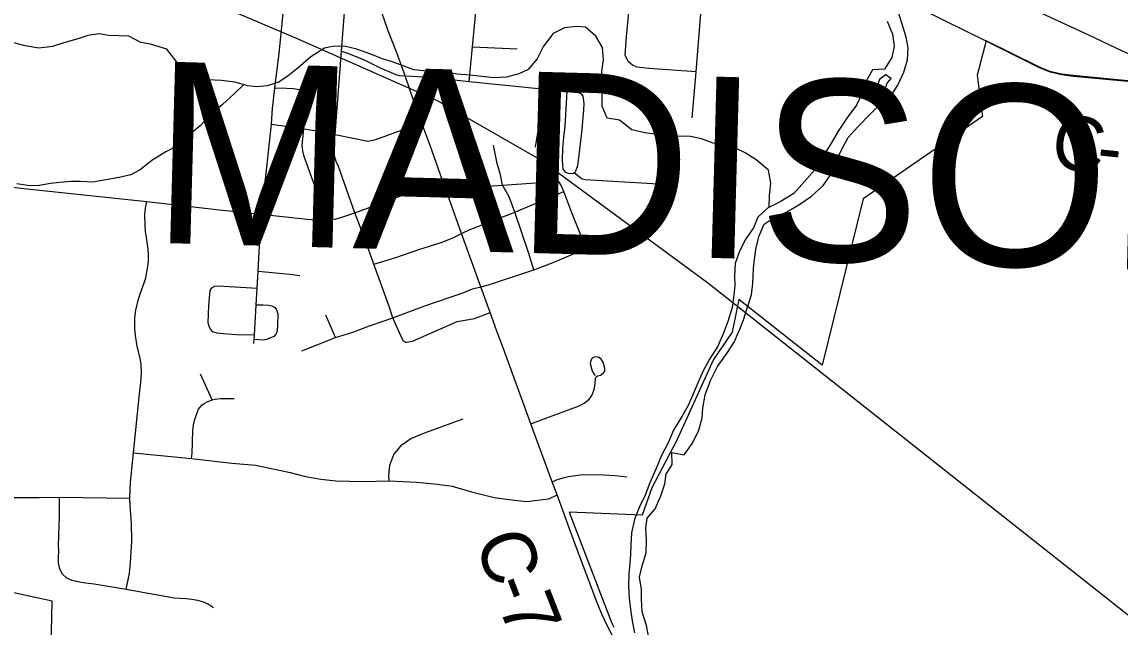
# Model space of a CAD drawing. Extents: x 114843 to 284848, y 317643 to 566895.
# Drawn here: x 129491 to 135543, y 436168 to 439505 of the extents above; entities that cross this region are included whole.
import ezdxf

# ---------------------------------------------------------------- set-up
doc = ezdxf.new("R2010")
doc.units = 0
for name, color, linetype in [('GM_X_City_Street', 7, 'Continuous'), ('GM_X_Corporation', 7, 'Continuous'), ('GM_X_County_Road', 7, 'Continuous'), ('GM_X_County_Road_Text', 7, 'Continuous'), ('GM_X_County_Text', 7, 'Continuous'), ('GM_X_Major_River', 7, 'Continuous'), ('GM_X_Minor_River', 7, 'Continuous'), ('GM_X_Rail_Line', 7, 'Continuous'), ('GM_X_State_Route', 7, 'Continuous')]:
    doc.layers.add(name, color=color, linetype=linetype)

msp = doc.modelspace()

# ---------------------------------------------------------------- linework, layer by layer
at = {"layer": 'GM_X_City_Street'}
for p, q in [((131974, 439367.9), (132221.3, 439357.5)), ((131219.3, 437764.1), (131166.5, 437887.7)), ((130539.9, 437421.5), (130475.5, 437562))]:
    msp.add_line(p, q, dxfattribs=at)
for points in [[(130808.9, 438444.4), (130818.4, 438511.8), (130840.9, 438705.1), (130865.5, 438942.2), (130872.7, 439027.6), (130885.3, 439140.6), (130908.8, 439332.6), (130936.7, 439607.5), (130946.1, 439685.4), (130964.3, 439843.2), (130982.9, 440026.2), (130985, 440064.6)], [(131605.6, 437738.7), (131600.2, 437740.5), (131594.5, 437745.9), (131589.3, 437753.8), (131535.3, 437873.4), (131512.5, 437942.1), (131430.5, 438169.5), (131379.9, 438309.9), (131326, 438452.4), (131235.2, 438707.1), (131222.1, 438736.4), (131212.7, 438767.2), (131207, 438799), (131217.8, 438883.9), (131251.6, 439343.4), (131276.1, 439653.8), (131289.2, 439816.3), (131292, 440035.2)], [(131955.1, 439176.1), (131974, 439367.9), (131992.9, 439561.3), (132010.4, 439750.3), (132022.1, 439864.4), (132028.3, 439962.7)], [(132832.5, 439286.8), (132816.2, 439321.9), (132823.7, 439422.2), (132867.9, 439881.6)], [(133184.6, 438976.9), (133206.8, 439229.7), (133232.2, 439551.5), (133253.3, 439749.9), (133267.4, 439843.6)], [(131251.6, 439343.4), (131285.6, 439332.7), (131373.4, 439297.1), (131464.9, 439252.8), (131551.8, 439216), (131570.6, 439210.5), (131602.7, 439207.3), (131743.3, 439201.1), (131955.1, 439176.1), (132355.9, 439135.7), (132496.3, 439121.9), (132553.1, 439116.9), (132565.7, 439113.5), (132575.4, 439107.7), (132582.1, 439096.4), (132588, 439055.2), (132586.9, 439018.2), (132574.8, 438895.4), (132556.7, 438741.8), (132552.1, 438711), (132540.3, 438675.9), (132536.2, 438672.9)], [(133206.8, 439229.7), (132945.5, 439247.7), (132879.8, 439256.5), (132855.6, 439265.8), (132832.5, 439286.8)], [(131176.6, 438412.6), (131094.3, 438630), (131046.5, 438763.4), (131039.9, 438794.6), (131036, 438826.4), (131044.5, 438916.3), (131064.3, 439082.1), (131066.4, 439113.2), (131064.3, 439115.8), (131039.1, 439125.2), (131009.6, 439132.4), (130987.1, 439135.7), (130948.9, 439138.6), (130885.3, 439140.6)], [(132355.9, 439135.7), (132355.2, 439069.2), (132341.3, 438995.8), (132338.6, 438975.6), (132333.9, 438904.9), (132320.2, 438814.9)], [(132536.2, 438672.9), (132530.4, 438668.5), (132513, 438668), (132503, 438669), (132489.1, 438675.5), (132478.9, 438685.1), (132474.8, 438693.1), (132472, 438715.5), (132470.8, 438746.2), (132472.6, 438807.8), (132478, 438869.3), (132485.5, 438930.6), (132496.3, 439121.9)], [(130865.5, 438942.2), (131044.5, 438916.3), (131129.9, 438903.2), (131217.8, 438883.9), (131396.9, 438848.4), (131433.3, 438855.1), (131488.1, 438872.7), (131552.3, 438897.4), (131694.5, 438947)], [(132311.9, 438138.6), (132282.5, 438233), (132206.8, 438456.5), (132175.8, 438540.3), (132139.8, 438604.1), (132128.5, 438661.4), (132109.9, 438724.9), (132090.8, 438825.1)], [(128022.6, 438748.3), (128278.4, 438722.7), (128595.2, 438687.5), (129311.7, 438607.9), (129484.1, 438588.2), (130178.3, 438514.1), (130580.1, 438468.7), (130808.9, 438444.4), (131062.1, 438417.6), (131126.5, 438412.5), (131176.6, 438412.6), (131191.4, 438413.5), (131223.2, 438419.9), (131254.8, 438428.4), (131326, 438452.4), (131809, 438630.5)], [(132536.2, 438672.9), (132579.1, 438639.9), (132594.9, 438636), (133059.7, 438609.1)], [(131826.6, 438580.3), (131928.3, 438589.5), (132139.8, 438604.1), (132320.6, 438617.4), (132419.9, 438629.6), (132436.4, 438629.5), (132448.5, 438627.2)], [(132603, 438251.3), (132521.9, 438452.7), (132477.6, 438569.5), (132462.8, 438604), (132448.5, 438627.2)], [(131430.5, 438169.5), (131556.6, 438208.6), (131679, 438250), (131802.1, 438289.5), (131862.7, 438312.4), (131913.8, 438338.9), (131955.8, 438359.6), (132189.7, 438448.5), (132206.8, 438456.5), (132477.6, 438569.5)], [(130066, 436377.4), (130078.5, 436437.4), (130082.8, 436466.3), (130088.3, 436524.5), (130095.7, 436641), (130095, 436739.3), (130086.6, 436837), (130084.8, 436878.1), (130089.4, 436967.4), (130105, 437129.9), (130138.5, 437454.6), (130146.4, 437519.4), (130149.5, 437567.6), (130147.5, 437617.1), (130142.2, 437649.3), (130126.3, 437717.8), (130116.6, 437776.8), (130112.9, 437816.2), (130113.9, 437874), (130118.9, 437915.5), (130131.5, 437969.7), (130140.4, 438000.9), (130172.9, 438092.5), (130176.2, 438106.2), (130185.1, 438156), (130188.3, 438188.2), (130188.1, 438220.6), (130185.9, 438252.9), (130178, 438317.1), (130171.2, 438350), (130169.2, 438380.5), (130168.9, 438445.8), (130171.8, 438478.1), (130178.3, 438514.1)], [(130769, 437731.1), (130770.4, 437754.4), (130771.7, 437777), (130781.7, 437944.8), (130787.6, 438036.6), (130792.6, 438131.1), (130808.9, 438444.4)], [(132020.3, 438045.1), (132061.6, 438055.5), (132311.9, 438138.6), (132419.3, 438178.4), (132539.3, 438229.5), (132603, 438251.3), (132814, 438341.3)], [(130792.6, 438131.1), (130967.1, 438114.3), (131021.8, 438107.4)], [(130771.7, 437777), (130672.9, 437780.4), (130599.9, 437784.8), (130565.9, 437788.2), (130542.7, 437796.5), (130530.5, 437811), (130521.9, 437826.7), (130518.1, 437846.2), (130521, 437942.2), (130527.7, 438024.9), (130537.4, 438039.5), (130553.1, 438048.2), (130572.5, 438049.5), (130787.6, 438036.6)], [(131033.9, 437690.9), (131219.3, 437764.1), (131315, 437794.4), (131406.1, 437828.8), (131535.3, 437873.4), (131711.7, 437939.1), (131927.1, 438012.6), (131973.9, 438033.4), (132020.3, 438045.1)], [(130781.7, 437944.8), (130821, 437945.1), (130849.2, 437943.3), (130868.6, 437939.8), (130884.5, 437930.2), (130894.3, 437918.1), (130901.8, 437896.3), (130899.3, 437833.5), (130897.1, 437801.5), (130892.8, 437785.7), (130878.4, 437771), (130838.4, 437753.7), (130820.8, 437750.9), (130770.4, 437754.4)], [(131605.6, 437738.7), (131611.6, 437738.6), (131643.6, 437745.5), (131890.3, 437853.1), (131984.6, 437869.5), (132071.5, 437903.3)], [(132296.2, 437288.5), (132384.7, 437322.9), (132562, 437388.6), (132590.5, 437403.1), (132615.2, 437422.9), (132625.4, 437435), (132633.6, 437448.3), (132644.7, 437478), (132649.5, 437509.6), (132651.3, 437538.1), (132655.9, 437548.1), (132662.8, 437554.2), (132680.3, 437558), (132694.8, 437567.6), (132702.8, 437579.3), (132703.4, 437593.9), (132694.4, 437628.1), (132684.1, 437646.3), (132668.7, 437656.4), (132650.4, 437657.7), (132633.7, 437650.3), (132626.5, 437638.6), (132623.7, 437622.5), (132631.2, 437586.8), (132641.6, 437567.2), (132650.4, 437554.9)], [(130425, 437097.8), (130428.3, 437127.8), (130432.3, 437250.3), (130435.9, 437281), (130443.1, 437313.9), (130464.1, 437370.3), (130482.5, 437392.6), (130494.9, 437401.9), (130508, 437409.2), (130539.9, 437421.5), (130556.7, 437425.5), (130585.2, 437428.1), (130659.8, 437428.7)], [(131515.5, 436974.3), (131513, 436999.7), (131517.7, 437061), (131540.7, 437119.7), (131584.2, 437172.7), (131633.8, 437208.2), (131715.5, 437240.9), (131922.7, 437315.6)], [(130105, 437129.9), (130425, 437097.8), (130647.5, 437071.3), (130780, 437061.6), (130970, 437019.7), (131053.2, 436998.1), (131137.6, 436982.9), (131221, 436974.6), (131370.4, 436970.1), (131515.5, 436974.3), (131667.1, 436967.5), (131781.3, 436956.4), (131862.7, 436944.5), (131968.8, 436913.9), (132094.4, 436883.5), (132161.8, 436872.9), (132221.9, 436865.4), (132272.5, 436861.1), (132394.1, 436875.8), (132441.1, 436896.6)], [(132414.1, 436969.7), (132443.5, 436982.1), (132473.5, 436991.8), (132503.7, 436998.9), (132567.9, 437007), (132631.9, 437008.8), (132696, 437007.7), (132760, 437003.2), (132824.2, 436996.6)], [(128955.7, 436827.1), (128993.1, 436853.6), (129032.2, 436871.9), (129072.6, 436884.9), (129095.6, 436890), (129130, 436894.6), (129171.4, 436895.7), (129388.4, 436882.8), (129584.8, 436882.9), (129696.8, 436884.6), (130084.8, 436878.1)], [(129696.8, 436884.6), (129695.9, 436780), (129691.3, 436618.3), (129692.1, 436586), (129689.7, 436553.8), (129690.5, 436521.4), (129698.1, 436490.1), (129712.9, 436461.7), (129736, 436440.5), (129765.8, 436427.7), (129827.4, 436414.8), (129858.1, 436409.9), (129889.6, 436407), (130066, 436377.4), (130330.4, 436330.3), (130393.8, 436326.2), (130426.5, 436322.5), (130458.5, 436316.5), (130489.7, 436307.2), (130519.4, 436294), (130547.2, 436276.5)]]:
    msp.add_lwpolyline(points, dxfattribs=at)
at = {"layer": 'GM_X_Corporation'}
for points in [[(135643.3, 439175.5), (135285.3, 439208.9), (135220.6, 439218), (135156.9, 439232.7), (135096.2, 439257.6), (134806.5, 439401.1), (134755.3, 439210.7), (134785.4, 438984.2), (134128.4, 438529), (133901.8, 437611.9), (133442.1, 437973.9), (133405.4, 437794.3), (133303.5, 437643.3), (133099.8, 437198.2), (132962.4, 436936.5), (132909, 436785.9), (132506.8, 436802.2), (132670.8, 436374.9), (132742, 436189.3), (132753.3, 436167.7)], [(129645, 435715.4), (129656.5, 436310.5), (128946.9, 436465.4)]]:
    msp.add_lwpolyline(points, dxfattribs=at)
at = {"layer": 'GM_X_County_Road'}
for p, q in [((131826.6, 438580.3), (131809, 438630.5)), ((131913.8, 438338.9), (131826.6, 438580.3)), ((132020.3, 438045.1), (131913.8, 438338.9)), ((132071.5, 437903.3), (132020.3, 438045.1)), ((132414.1, 436969.7), (132296.2, 437288.5)), ((132441.1, 436896.6), (132414.1, 436969.7))]:
    msp.add_line(p, q, dxfattribs=at)
for points in [[(131602.7, 439207.3), (131557.2, 439335.2), (131509.1, 439456.5), (131456.3, 439611), (131411.7, 439733.8), (131387.4, 439808.8)], [(134265.5, 439747.4), (134287.9, 439722.2), (134326.2, 439672.3), (134347.5, 439647.5), (134453.7, 439573.6), (134807.7, 439398.2)], [(134807.7, 439398.2), (135097.4, 439254.7), (135158.1, 439229.9), (135221.8, 439215.2), (135286.5, 439206.1), (135644.5, 439172.7), (135883, 439146), (135978.9, 439141.9), (136086.1, 439159.8)], [(131694.5, 438947), (131654.3, 439058), (131602.7, 439207.3)], [(131809, 438630.5), (131740.5, 438823.2), (131694.5, 438947)], [(132296.2, 437288.5), (132144, 437708.1), (132108.2, 437799.2), (132071.5, 437903.3)], [(132477.2, 436796.6), (132475.4, 436801.5), (132441.1, 436896.6)], [(132664.9, 436292.5), (132536, 436635.3), (132477.2, 436796.6)], [(132752.1, 436108.4), (132749.2, 436113.3), (132714.1, 436179.6), (132688.1, 436234.9), (132664.9, 436292.5)]]:
    msp.add_lwpolyline(points, dxfattribs=at)
at = {"layer": 'GM_X_Major_River'}
for points in [[(132946.7, 436108.2), (132932.9, 436176.4), (132909.2, 436252.6), (132905.5, 436322.8), (132905.7, 436374.9), (132893.9, 436443.2), (132910.2, 436505.2), (132930.6, 436577.4), (132932.9, 436647.5), (132929.1, 436713.7), (132937.4, 436767.8), (132981.6, 436819.8), (133012, 436891.8), (133034.3, 436957.9), (133042.5, 437012), (133074.8, 437064), (133073.1, 437130.2), (133141.1, 437117.9), (133187.5, 437181.9), (133221.8, 437254), (133240.1, 437322.1), (133244.3, 437376.2), (133256.7, 437448.3), (133287, 437528.4), (133325.4, 437604.5), (133375.8, 437676.5), (133416.1, 437738.5), (133448.5, 437810.5), (133468.7, 437862.6), (133489, 437926.7), (133511.3, 438000.8), (133519.6, 438064.9), (133524, 438145.1), (133528.2, 438197.2), (133538.5, 438261.3), (133554.8, 438325.4), (133581.1, 438389.5), (133631.3, 438423.4), (133707.5, 438457.2), (133773.8, 438497), (133842.1, 438544.9), (133906.5, 438602.8), (133954.8, 438670.8), (133977.1, 438732.9), (134007.4, 438799), (134045.8, 438867), (134098.1, 438926.9), (134168.5, 438998.9), (134228.8, 439056.8), (134281.1, 439098.7), (134319.4, 439156.7), (134351.7, 439228.8), (134372, 439296.9), (134376.3, 439363), (134364.5, 439421.2), (134342.8, 439493.5), (134317.1, 439573.7)], [(134260.8, 439509.8), (134288.5, 439437.5), (134298.2, 439371.3), (134286, 439309.2), (134245.6, 439245.2), (134179.5, 439241.4), (134143.2, 439175.4), (134120.9, 439109.3), (134090.6, 439045.3), (134038.2, 438975.3), (133989.8, 438903.3), (133949.5, 438833.2), (133899.1, 438755.2), (133858.7, 438687.2), (133804.4, 438625.2), (133746, 438559.3), (133669.7, 438513.4), (133599.4, 438477.6), (133547.2, 438427.7), (133522.9, 438369.6), (133480.6, 438309.6), (133446.2, 438241.6), (133421.9, 438173.5), (133417.6, 438103.3), (133419.4, 438051.2), (133415.2, 438001.1), (133404.9, 437931), (133382.5, 437852.9), (133356.2, 437784.8), (133325.9, 437716.7), (133281.5, 437644.7), (133243.2, 437576.7), (133212.8, 437506.6), (133186.5, 437444.6), (133162.3, 437390.5), (133128, 437328.5), (133081.6, 437254.5), (133053.3, 437184.4), (133016.9, 437114.4), (132986.6, 437042.3), (132952.2, 436964.2), (132925.9, 436896.1), (132893.5, 436828.1), (132867.2, 436762), (132850.9, 436687.9), (132846.6, 436619.7), (132844.4, 436569.6), (132842.2, 436517.5), (132835.9, 436463.4), (132833.6, 436395.3), (132837.4, 436327.1), (132847.1, 436252.9), (132854.9, 436202.7), (132866.6, 436136.5)], [(134217.3, 439187.2), (134205.2, 439147.1), (134193, 439117.1), (134215, 439094.9), (134230.5, 439108.2)], [(134230.5, 439108.2), (134243.1, 439118.9), (134259.3, 439167), (134281.5, 439192.9), (134251.5, 439213.1), (134217.3, 439187.2)]]:
    msp.add_lwpolyline(points, dxfattribs=at)
at = {"layer": 'GM_X_Minor_River'}
for points in [[(133609.9, 438482.9), (133611.8, 438547.7), (133618, 438615.9), (133606.3, 438688.1), (133538.4, 438744.5), (133476.5, 438782.8), (133424.5, 438809), (133368.5, 438825.3), (133300.4, 438837.5), (133236.4, 438859.8), (133176.4, 438874.1), (133120.3, 438874.3), (133046.2, 438872.5), (132992.2, 438884.7), (132924.1, 438893), (132852, 438909.3), (132784.2, 438963.7), (132716.1, 438973.9), (132688.3, 439040.2), (132688.6, 439112.4), (132686.9, 439182.5), (132687.1, 439232.7), (132695.4, 439296.8), (132691.7, 439364.9), (132653.9, 439427.2), (132598, 439475.6), (132547.9, 439479.7), (132481.8, 439472), (132419.5, 439442.1), (132365.2, 439372.1), (132330.8, 439302.1), (132280.5, 439242.1), (132230.3, 439218.2), (132162.1, 439200.4), (132092, 439196.7), (132025.9, 439204.9), (131961.9, 439211.2), (131889.8, 439217.4), (131819.7, 439227.7), (131769.6, 439227.9), (131703.6, 439236.1), (131651.5, 439240.3), (131583.5, 439266.6), (131531.5, 439284.8), (131477.5, 439301.1), (131407.5, 439329.4), (131337.5, 439355.7), (131273.4, 439370), (131211.3, 439372.2), (131159.2, 439360.3), (131082.9, 439312.5), (131012.5, 439252.6), (130958.3, 439208.7), (130906, 439172.8), (130841.8, 439153), (130785.7, 439147.1), (130735.7, 439153.3), (130663.7, 439173.6), (130591.6, 439181.9), (130515.5, 439186.2), (130459.4, 439196.4), (130395.4, 439218.7), (130345.6, 439281), (130289.8, 439355.4), (130199.8, 439381.8), (130145.7, 439392), (130079.8, 439426.3), (130025.7, 439428.5), (129967.6, 439430.7), (129915.6, 439438.9), (129853.4, 439431.1), (129793.2, 439409.3), (129721, 439389.5), (129658.9, 439369.6), (129584.7, 439359.9), (129508.6, 439374.2), (129446.6, 439390.4)], [(130714.4, 439159.3), (130661.4, 439109.5), (130597, 439049.6), (130530.7, 438993.7), (130472.4, 438931.7), (130404, 438875.8), (130341.7, 438817.9), (130283.5, 438788), (130207.1, 438740.2), (130142.8, 438690.3), (130090.6, 438662.4), (130026.5, 438646.6), (129952.3, 438634.8), (129882.1, 438621), (129814, 438625.3), (129762, 438625.5), (129697.8, 438619.7), (129647.7, 438613.8), (129585.6, 438604), (129533.5, 438602.2), (129463.4, 438612.5)]]:
    msp.add_lwpolyline(points, dxfattribs=at)
at = {"layer": 'GM_X_Rail_Line'}
msp.add_lwpolyline([(128478.6, 440489.4), (130998.1, 439417.9), (131779.8, 439072.5), (132352.2, 438743.3), (133270.1, 438068.7), (136073.7, 435851.8), (137428.7, 434712.6), (140276.2, 432131.7), (143769.3, 428946.1), (146519.3, 426434.1), (147203, 425812.1)], dxfattribs=at)
at = {"layer": 'GM_X_State_Route'}
msp.add_lwpolyline([(133953.9, 439777.4), (134265.5, 439747.4), (134475.9, 439725), (134541, 439716.3), (134637.8, 439699.9), (134702.1, 439686.7), (134765.9, 439671.4), (134860.8, 439645.2), (134923.4, 439625.6), (135016.1, 439593), (135106.8, 439555.6), (135373.3, 439432), (135551.9, 439347), (135611.5, 439320), (135702.3, 439281.7), (135794.1, 439246.8), (135887, 439215.1), (135981.2, 439187), (136086.1, 439159.8)], dxfattribs=at)

# ---------------------------------------------------------------- texts
at = {"layer": 'GM_X_County_Road_Text'}
for s, rotation, p in [('C', 352.58493, (135154.8, 438704.3)), ('-', 354.09614, (135407.7, 438671.5)), ('C', 289.35234, (131984.8, 436646)), ('-', 290.95009, (132069.6, 436405)), ('7', 291.4015, (132114.6, 436287.5))]:
    msp.add_text(s, height=300, rotation=rotation, dxfattribs=at).set_placement(p)
at = {"layer": 'GM_X_County_Text'}
msp.add_text('MADISON COUNTY', height=1000.028, rotation=358.44093, dxfattribs=at).set_placement((130198.2, 438288.1))

doc.saveas('drawing.dxf')
